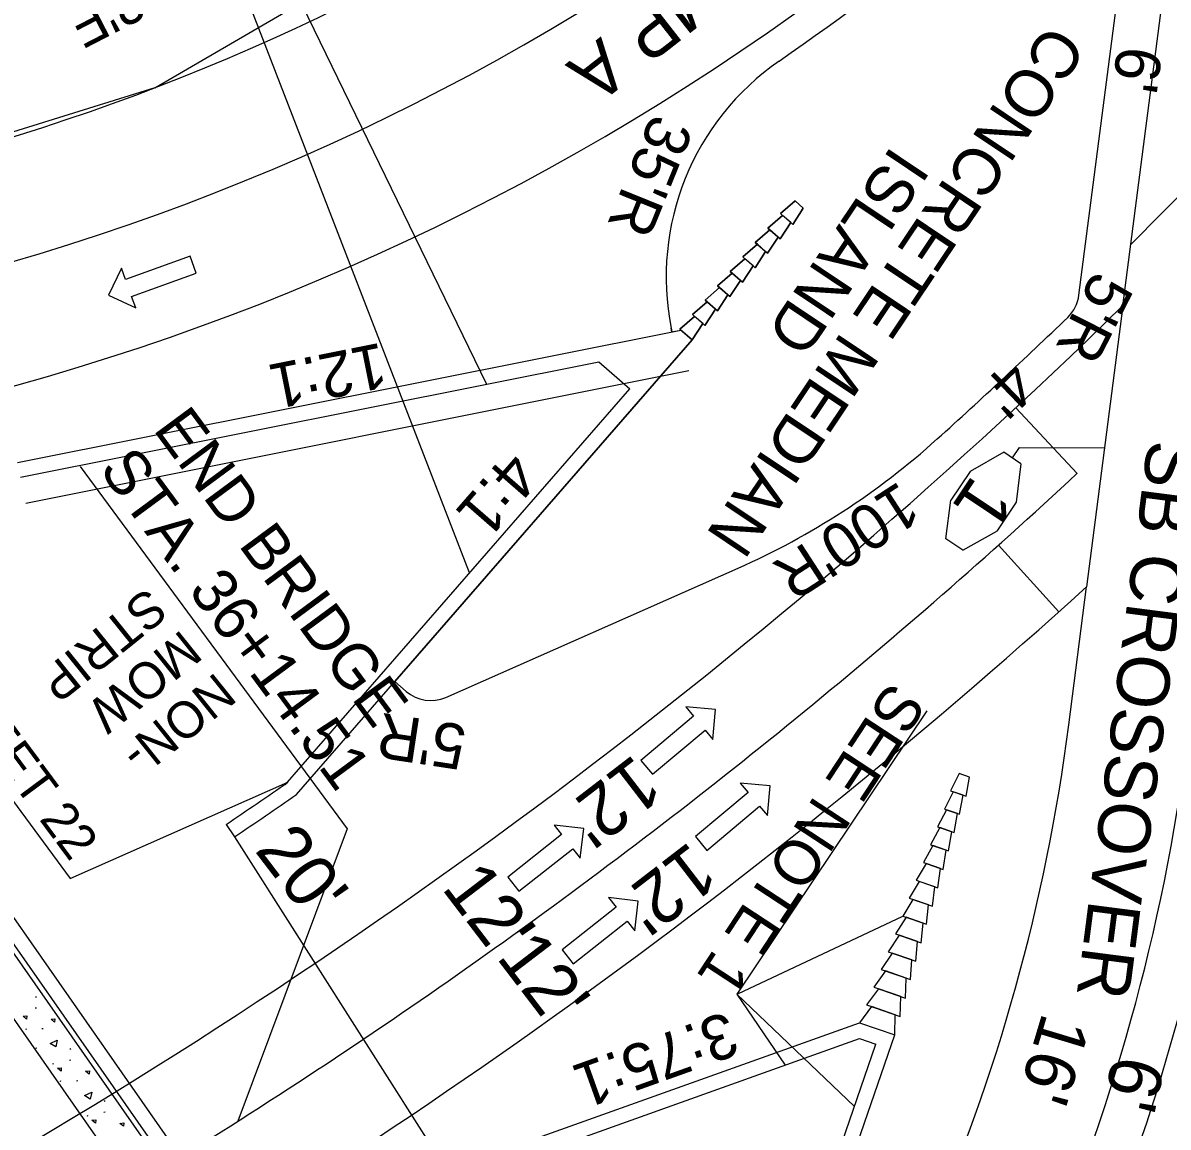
# Model space of a CAD drawing. Extents: x 1966090 to 1975830, y 788086 to 801233.
# Drawn here: x 1971441.1 to 1971594, y 796145.9 to 796293.3 of the extents above; entities that cross this region are included whole.
import ezdxf

# ---------------------------------------------------------------- set-up
doc = ezdxf.new("R2010")
doc.units = 0
for name, color, linetype in [('BR_PRESTRESSED BEAM', 7, 'Continuous'), ('BR_PROPOSED_DRAINAGE', 7, 'Continuous'), ('BR_PROPOSED_TRAVELWAY', 7, 'Continuous'), ('BR_REBAR', 7, 'Continuous'), ('BR_SITE LOCATION', 7, 'Continuous'), ('RD_EX_Driveway_txCode', 7, 'Continuous'), ('RD_EX_SU_Gas', 7, 'Continuous'), ('RD_EX_SU_SwpLmt', 7, 'Continuous'), ('RD_EX_TX_BldgApp_ELEV', 7, 'Continuous'), ('RD_EX_TX_Dam_ELEV', 7, 'Continuous'), ('RD_HY_XS_Slope', 7, 'Continuous'), ('RD_PD_RW_TX', 7, 'Continuous'), ('RD_Sketch6', 7, 'Continuous'), ('RD_Sketch8', 7, 'Continuous')]:
    doc.layers.add(name, color=color, linetype=linetype)

msp = doc.modelspace()

# ---------------------------------------------------------------- linework, layer by layer
at = {"layer": 'BR_PRESTRESSED BEAM'}
for q in [(1971520.97, 796320.88), (1971423.44, 796273.61)]:
    msp.add_line((1971458.75, 796284.65), q, dxfattribs=at)
at = {"layer": 'BR_PROPOSED_DRAINAGE'}
msp.add_lwpolyline([(1971355.49, 796296.53), (1971379.93, 796260.39), (1971397.2, 796235.33), (1971416.64, 796207.13), (1971494.67, 796095.38), (1971512.27, 796070.43)], dxfattribs=at)
at = {"layer": 'BR_PROPOSED_TRAVELWAY'}
for p, q in [((1971582.1, 796256.96), (1971587.53, 796299.08)), ((1971582.1, 796256.96), (1971587.53, 796299.08)), ((1971542.26, 796267.85), (1971544.21, 796269.54)), ((1971545.31, 796268.58), (1971543.91, 796266.41)), ((1971544.21, 796269.54), (1971545.31, 796268.58)), ((1971540.58, 796265.92), (1971542.53, 796267.61)), ((1971542.53, 796267.61), (1971542.26, 796267.85)), ((1971538.9, 796264), (1971540.86, 796265.68)), ((1971540.86, 796265.68), (1971540.58, 796265.92)), ((1971543.64, 796266.65), (1971542.23, 796264.48)), ((1971543.91, 796266.41), (1971543.64, 796266.65)), ((1971539.18, 796263.76), (1971538.9, 796264)), ((1971541.96, 796264.72), (1971540.55, 796262.56)), ((1971542.23, 796264.48), (1971541.96, 796264.72)), ((1971537.22, 796262.07), (1971539.18, 796263.76)), ((1971540.28, 796262.8), (1971538.88, 796260.63)), ((1971540.55, 796262.56), (1971540.28, 796262.8)), ((1971535.55, 796260.14), (1971537.5, 796261.83)), ((1971538.6, 796260.87), (1971537.2, 796258.7)), ((1971537.5, 796261.83), (1971537.22, 796262.07)), ((1971538.88, 796260.63), (1971538.6, 796260.87)), ((1971533.87, 796258.21), (1971535.82, 796259.9)), ((1971535.82, 796259.9), (1971535.55, 796260.14)), ((1971532.19, 796256.29), (1971534.14, 796257.97)), ((1971534.14, 796257.97), (1971533.87, 796258.21)), ((1971536.92, 796258.94), (1971535.52, 796256.78)), ((1971537.2, 796258.7), (1971536.92, 796258.94)), ((1971532.47, 796256.05), (1971532.19, 796256.29)), ((1971535.24, 796257.01), (1971533.84, 796254.85)), ((1971535.52, 796256.78), (1971535.24, 796257.01)), ((1971530.51, 796254.36), (1971532.47, 796256.05)), ((1971533.57, 796255.09), (1971532.16, 796252.92)), ((1971533.84, 796254.85), (1971533.57, 796255.09)), ((1971528.83, 796252.43), (1971530.79, 796254.12)), ((1971531.89, 796253.16), (1971530.49, 796250.99)), ((1971530.79, 796254.12), (1971530.51, 796254.36)), ((1971532.16, 796252.92), (1971531.89, 796253.16)), ((1971527.78, 796252.07), (1971527.68, 796252.57)), ((1971527.68, 796252.57), (1971527.78, 796252.07)), ((1971527.78, 796252.07), (1971528.98, 796252.31)), ((1971528.98, 796252.31), (1971528.83, 796252.43)), ((1971530.49, 796250.99), (1971490.78, 796205.39)), ((1971497.59, 796203.27), (1971536.62, 796220.53)), ((1971497.59, 796203.27), (1971536.62, 796220.53)), ((1971490.78, 796205.39), (1971492.29, 796204.08)), ((1971490.78, 796205.39), (1971492.29, 796204.08))]:
    msp.add_line(p, q, dxfattribs=at)
for points in [[(1971538.6, 796260.87), (1971538.6, 796260.87)], [(1971536.92, 796258.94), (1971536.92, 796258.94)], [(1971535.24, 796257.01), (1971535.24, 796257.01)], [(1971530.79, 796254.12), (1971530.79, 796254.12)], [(1971531.89, 796253.16), (1971531.89, 796253.16)]]:
    msp.add_lwpolyline(points, dxfattribs=at)
for centre, radius, start, end in [((1971352.19, 796562.97), 334, 304.6524, 315.4027), ((1971352.19, 796562.97), 334, 304.6524, 315.4027), ((1971562, 796259.42), 35, 124.6524, 191.2971), ((1971562, 796259.42), 35, 124.6524, 191.2971), ((1971577.14, 796257.6), 5, 313.8618, 352.6496), ((1971577.14, 796257.6), 5, 313.8618, 352.6496), ((1971051.22, 796804.85), 764, 312.07619, 313.8618), ((1971051.22, 796804.85), 764, 312.07619, 313.8618), ((1971496.17, 796311.99), 100, 293.8568, 312.0762), ((1971496.17, 796311.99), 100, 293.8568, 312.0762), ((1971495.57, 796207.85), 5, 228.9555, 293.8568), ((1971495.57, 796207.85), 5, 228.9555, 293.8568)]:
    msp.add_arc(centre, radius, start, end, dxfattribs=at)
at = {"layer": 'BR_REBAR'}
for p, q in [((1971440.43, 796234.62), (1971528.98, 796252.31)), ((1971530.49, 796250.99), (1971528.98, 796252.31)), ((1971477.65, 796190.31), (1971530.49, 796250.99)), ((1971440.82, 796232.66), (1971518, 796248.07)), ((1971518, 796248.07), (1971522.15, 796244.46)), ((1971476.14, 796191.62), (1971522.15, 796244.46)), ((1971468.28, 796186.32), (1971469.39, 796184.66)), ((1971502.52, 796141.9), (1971552.8, 796159.85)), ((1971552.8, 796159.85), (1971557.52, 796158.22)), ((1971503.19, 796140.02), (1971552.81, 796157.73)), ((1971536.89, 796104.51), (1971554.98, 796156.98)), ((1971538.78, 796103.86), (1971557.52, 796158.22)), ((1971552.81, 796157.73), (1971554.98, 796156.98))]:
    msp.add_line(p, q, dxfattribs=at)
for points in [[(1971358.49, 796293.18), (1971359.61, 796291.14), (1971363.68, 796284.48), (1971364.94, 796282.55), (1971379.93, 796260.39), (1971397.2, 796235.33), (1971416.64, 796207.13), (1971494.67, 796095.38), (1971512.27, 796070.43)], [(1971356.73, 796292.22), (1971357.88, 796290.13), (1971361.99, 796283.41), (1971363.28, 796281.44), (1971378.28, 796259.26), (1971395.55, 796234.19), (1971414.99, 796205.99), (1971493.03, 796094.24), (1971510.62, 796069.31)]]:
    msp.add_lwpolyline(points, dxfattribs=at)
for centre, radius, start, end in [((1971051.22, 796804.85), 746, 303.99104, 304.75703), ((1971051.22, 796804.85), 748, 303.99104, 304.75703), ((1971332.81, 796231.61), 272, 336.2104, 348.0583)]:
    msp.add_arc(centre, radius, start, end, dxfattribs=at)
at = {"layer": 'BR_SITE LOCATION'}
for p, q in [((1971442.94, 796163.32), (1971442.81, 796163.22)), ((1971442.76, 796161.82), (1971442.94, 796161.85)), ((1971441.57, 796159.02), (1971441.51, 796158.89)), ((1971443.68, 796159.06), (1971443.86, 796159.09)), ((1971442.82, 796156.47), (1971443, 796156.5)), ((1971447.54, 796156.38), (1971447.41, 796156.27)), ((1971445.18, 796154.4), (1971445.13, 796154.28)), ((1971447.36, 796154.87), (1971447.54, 796154.9)), ((1971446.17, 796152.07), (1971446.12, 796151.94)), ((1971448.28, 796152.11), (1971448.46, 796152.14)), ((1971447.46, 796149.53), (1971447.6, 796149.55)), ((1971452.14, 796149.43), (1971452.01, 796149.32)), ((1971451.96, 796147.92), (1971452.14, 796147.95)), ((1971449.78, 796147.46), (1971449.73, 796147.33))]:
    msp.add_line(p, q, dxfattribs=at)
for points in [[(1971356.11, 796291.89), (1971357.26, 796289.78), (1971361.39, 796283.03), (1971362.69, 796281.05), (1971377.69, 796258.87), (1971394.97, 796233.79), (1971414.41, 796205.59), (1971492.45, 796093.83), (1971517.1, 796058.89)], [(1971351.73, 796289.49), (1971352.93, 796287.27), (1971357.17, 796280.35), (1971358.53, 796278.28), (1971373.56, 796256.05), (1971390.85, 796230.96), (1971410.3, 796202.74), (1971488.36, 796090.96), (1971513.02, 796056.01)], [(1971441.16, 796160.72), (1971441.67, 796160.79), (1971441.64, 796160.33), (1971441.16, 796160.72)], [(1971444.9, 796160.31), (1971445.41, 796160.38), (1971445.38, 796159.92), (1971444.9, 796160.31)], [(1971444.76, 796157.07), (1971445.72, 796157.54), (1971445.52, 796156.61), (1971444.78, 796157.06)], [(1971445.76, 796153.77), (1971446.27, 796153.84), (1971446.24, 796153.38), (1971445.76, 796153.77)], [(1971449.5, 796153.36), (1971450.01, 796153.43), (1971449.98, 796152.97), (1971449.5, 796153.36)], [(1971449.36, 796150.13), (1971450.32, 796150.59), (1971450.12, 796149.66), (1971449.38, 796150.12)], [(1971450.36, 796146.82), (1971450.87, 796146.89), (1971450.84, 796146.43), (1971450.36, 796146.82)], [(1971454.1, 796146.41), (1971454.61, 796146.48), (1971454.59, 796146.02), (1971454.1, 796146.41)]]:
    msp.add_lwpolyline(points, dxfattribs=at)
at = {"layer": 'RD_EX_Driveway_txCode'}
for points in [[(1971464.28, 796259.91), (1971463.46, 796262.17), (1971454.84, 796259.04), (1971454.28, 796260.58), (1971452.58, 796256.95), (1971456.21, 796255.26), (1971455.65, 796256.79)], [(1971523.63, 796194.87), (1971525.18, 796193.03), (1971532.21, 796198.91), (1971533.25, 796197.66), (1971533.61, 796201.65), (1971529.62, 796202), (1971530.67, 796200.75)], [(1971530.91, 796184.69), (1971532.45, 796182.85), (1971539.48, 796188.74), (1971540.53, 796187.49), (1971540.88, 796191.47), (1971536.9, 796191.82), (1971537.94, 796190.58)], [(1971505.85, 796179.28), (1971507.33, 796177.4), (1971514.54, 796183.08), (1971515.54, 796181.8), (1971516.01, 796185.77), (1971512.04, 796186.24), (1971513.05, 796184.96)], [(1971513.11, 796169.59), (1971514.6, 796167.71), (1971521.8, 796173.39), (1971522.81, 796172.11), (1971523.28, 796176.08), (1971519.31, 796176.55), (1971520.32, 796175.27)]]:
    msp.add_lwpolyline(points, close=True, dxfattribs=at)
at = {"layer": 'RD_EX_SU_Gas'}
for p, q in [((1971607.58, 796282.5), (1971589.03, 796263.74)), ((1971587.97, 796255.56), (1971583.13, 796218.05)), ((1971573.66, 796241.91), (1971581.87, 796233.18)), ((1971571.36, 796223.6), (1971579.43, 796214.69))]:
    msp.add_line(p, q, dxfattribs=at)
for start, end in [(305.76044, 312.8692), (298.92325, 306.04973)]:
    msp.add_arc((1971051.22, 796804.85), 780, start, end, dxfattribs=at)
at = {"layer": 'RD_EX_TX_BldgApp_ELEV'}
for p, q in [((1971544.21, 796269.54), (1971542.26, 796267.85)), ((1971543.91, 796266.41), (1971545.31, 796268.58)), ((1971545.31, 796268.58), (1971544.21, 796269.54)), ((1971542.53, 796267.61), (1971540.58, 796265.92)), ((1971542.26, 796267.85), (1971543.91, 796266.41)), ((1971543.64, 796266.65), (1971542.53, 796267.61)), ((1971540.86, 796265.68), (1971538.9, 796264)), ((1971540.58, 796265.92), (1971542.23, 796264.48)), ((1971541.96, 796264.72), (1971540.86, 796265.68)), ((1971542.23, 796264.48), (1971543.64, 796266.65)), ((1971538.9, 796264), (1971540.55, 796262.56)), ((1971540.55, 796262.56), (1971541.96, 796264.72)), ((1971539.18, 796263.76), (1971537.22, 796262.07)), ((1971538.88, 796260.63), (1971540.28, 796262.8)), ((1971540.28, 796262.8), (1971539.18, 796263.76)), ((1971537.5, 796261.83), (1971535.55, 796260.14)), ((1971537.2, 796258.7), (1971538.6, 796260.87)), ((1971537.22, 796262.07), (1971538.88, 796260.63)), ((1971538.6, 796260.87), (1971537.5, 796261.83)), ((1971535.82, 796259.9), (1971533.87, 796258.21)), ((1971535.55, 796260.14), (1971537.2, 796258.7)), ((1971536.92, 796258.94), (1971535.82, 796259.9)), ((1971536.37, 796259.42), (1971536.37, 796259.42)), ((1971534.14, 796257.97), (1971532.19, 796256.29)), ((1971533.87, 796258.21), (1971535.52, 796256.78)), ((1971535.24, 796257.01), (1971534.14, 796257.97)), ((1971535.52, 796256.78), (1971536.92, 796258.94)), ((1971532.19, 796256.29), (1971533.84, 796254.85)), ((1971533.84, 796254.85), (1971535.24, 796257.01)), ((1971532.47, 796256.05), (1971530.51, 796254.36)), ((1971532.16, 796252.92), (1971533.57, 796255.09)), ((1971533.57, 796255.09), (1971532.47, 796256.05)), ((1971530.79, 796254.12), (1971528.83, 796252.43)), ((1971530.49, 796250.99), (1971531.89, 796253.16)), ((1971530.51, 796254.36), (1971532.16, 796252.92)), ((1971531.89, 796253.16), (1971530.79, 796254.12)), ((1971528.83, 796252.43), (1971530.49, 796250.99)), ((1971566.13, 796193.1), (1971564.95, 796190.8)), ((1971567.51, 796192.62), (1971566.13, 796193.1)), ((1971567.03, 796190.09), (1971567.51, 796192.62)), ((1971565.33, 796190.67), (1971564.17, 796188.37)), ((1971564.95, 796190.8), (1971567.03, 796190.09)), ((1971566.65, 796190.22), (1971565.33, 796190.67)), ((1971566.14, 796187.69), (1971566.65, 796190.22)), ((1971564.42, 796188.28), (1971563.22, 796185.99)), ((1971564.17, 796188.37), (1971566.14, 796187.69)), ((1971565.89, 796187.77), (1971564.42, 796188.28)), ((1971565.43, 796185.23), (1971565.89, 796187.77)), ((1971563.22, 796185.99), (1971565.43, 796185.23)), ((1971563.51, 796185.89), (1971562.27, 796183.61)), ((1971565.14, 796185.33), (1971563.51, 796185.89)), ((1971564.71, 796182.78), (1971565.14, 796185.33)), ((1971562.6, 796183.5), (1971561.33, 796181.24)), ((1971562.27, 796183.61), (1971564.71, 796182.78)), ((1971564.38, 796182.89), (1971562.6, 796183.5)), ((1971563.99, 796180.32), (1971564.38, 796182.89)), ((1971561.69, 796181.11), (1971560.38, 796178.86)), ((1971561.33, 796181.24), (1971563.99, 796180.32)), ((1971563.62, 796180.45), (1971561.69, 796181.11)), ((1971563.27, 796177.86), (1971563.62, 796180.45)), ((1971560.78, 796178.72), (1971559.43, 796176.49)), ((1971560.38, 796178.86), (1971563.27, 796177.86)), ((1971562.87, 796178), (1971560.78, 796178.72)), ((1971562.55, 796175.41), (1971562.87, 796178)), ((1971559.94, 796176.31), (1971558.58, 796174.08)), ((1971559.43, 796176.49), (1971562.55, 796175.41)), ((1971562.04, 796175.58), (1971559.94, 796176.31)), ((1971561.74, 796172.99), (1971562.04, 796175.58)), ((1971559.02, 796173.92), (1971557.61, 796171.71)), ((1971558.58, 796174.08), (1971561.74, 796172.99)), ((1971561.3, 796173.14), (1971559.02, 796173.92)), ((1971561.04, 796170.53), (1971561.3, 796173.14)), ((1971558.1, 796171.54), (1971556.65, 796169.33)), ((1971557.61, 796171.71), (1971561.04, 796170.53)), ((1971560.55, 796170.69), (1971558.1, 796171.54)), ((1971560.33, 796168.06), (1971560.55, 796170.69)), ((1971557.18, 796169.15), (1971555.69, 796166.96)), ((1971556.65, 796169.33), (1971560.33, 796168.06)), ((1971559.81, 796168.25), (1971557.18, 796169.15)), ((1971558.49, 796168.7), (1971558.49, 796168.7)), ((1971559.63, 796165.6), (1971559.81, 796168.25)), ((1971556.26, 796166.77), (1971554.72, 796164.59)), ((1971555.69, 796166.96), (1971559.63, 796165.6)), ((1971559.06, 796165.8), (1971556.26, 796166.77)), ((1971554.72, 796164.59), (1971558.93, 796163.14)), ((1971558.93, 796163.14), (1971559.06, 796165.8)), ((1971555.34, 796164.38), (1971553.76, 796162.22)), ((1971558.31, 796163.35), (1971555.34, 796164.38)), ((1971558.23, 796160.68), (1971558.31, 796163.35)), ((1971554.42, 796162), (1971552.8, 796159.85)), ((1971553.76, 796162.22), (1971558.23, 796160.68)), ((1971557.57, 796160.91), (1971554.42, 796162)), ((1971557.52, 796158.22), (1971557.57, 796160.91)), ((1971552.8, 796159.85), (1971557.52, 796158.22))]:
    msp.add_line(p, q, dxfattribs=at)
at = {"layer": 'RD_EX_TX_Dam_ELEV'}
msp.add_line((1971469.39, 796184.66), (1971498.39, 796139.08), dxfattribs=at)
at = {"layer": 'RD_HY_XS_Slope'}
for p, q in [((1971572.08, 796235.99), (1971567.58, 796233.43)), ((1971574.35, 796234.47), (1971572.08, 796235.99)), ((1971567.58, 796233.43), (1971565, 796229.58)), ((1971574.35, 796234.47), (1971573.7, 796229.33)), ((1971564.35, 796224.44), (1971565, 796229.58)), ((1971573.7, 796229.33), (1971571.12, 796225.48)), ((1971566.62, 796222.92), (1971564.35, 796224.44)), ((1971566.62, 796222.92), (1971571.12, 796225.48))]:
    msp.add_line(p, q, dxfattribs=at)
msp.add_lwpolyline([(1971573.22, 796235.23), (1971574.16, 796236.63), (1971585.52, 796236.59)], dxfattribs=at)
at = {"layer": 'RD_PD_RW_TX'}
msp.add_arc((1971352.19, 796562.97), 298, 221.212, 301.3407, dxfattribs=at)
at = {"layer": 'RD_Sketch6'}
for p, q in [((1971500.77, 796219.91), (1971444.18, 796366.06)), ((1971441.51, 796229.22), (1971530.05, 796246.91)), ((1971448.78, 796234.11), (1971484.44, 796185.74)), ((1971561.79, 796201.49), (1971536.45, 796163.65)), ((1971484.44, 796185.74), (1971469.84, 796146.7)), ((1971536.56, 796163.7), (1971558.58, 796174.08)), ((1971536.45, 796163.65), (1971552.12, 796148.68)), ((1971536.45, 796163.65), (1971542.9, 796154.19))]:
    msp.add_line(p, q, dxfattribs=at)
for points in [[(1971471.47, 796406.81), (1971444.18, 796366.06), (1971503.03, 796245.08)], [(1971419.46, 796217.05), (1971447.43, 796179.11), (1971476.51, 796191.95)]]:
    msp.add_lwpolyline(points, dxfattribs=at)
at = {"layer": 'RD_Sketch8'}
for p, q in [((1971587.97, 796255.56), (1971593.49, 796298.31)), ((1971580.76, 796199.63), (1971583.13, 796218.05))]:
    msp.add_line(p, q, dxfattribs=at)
for centre, radius, start, end in [((1971352.19, 796562.97), 314, 221.212, 318.863), ((1971352.19, 796562.97), 330, 221.212, 316.8104), ((1971051.22, 796804.85), 768, 298.92325, 314.33883), ((1971051.22, 796804.85), 792, 298.92325, 312.19164), ((1971332.81, 796231.61), 250, 336.2104, 352.6496), ((1971332.81, 796231.61), 266, 336.2104, 352.6496)]:
    msp.add_arc(centre, radius, start, end, dxfattribs=at)

# ---------------------------------------------------------------- texts
at = {"layer": 'RD_EX_Driveway_txCode'}
for s, height, rotation, p in [('RAMP A', 7, 218.0606, (1971541.66, 796309.8)), ('CONCRETE MEDIAN', 6.3, 236.1913, (1971578.04, 796293.45)), ("6'", 6, 262.6496, (1971587.28, 796290.37)), ("35'R", 6, 247.9747, (1971525.17, 796281.41)), ('ISLAND', 6.3, 236.1913, (1971557.15, 796277.09)), ("5'R", 6, 243.2557, (1971584.18, 796260.45)), ('12:1', 6, 191.2971, (1971488.97, 796250.65)), ("4'", 6, 223.8618, (1971572.83, 796248.62)), ('SB CROSSOVER', 7, 262.651, (1971591.36, 796237.79)), ('4:1', 6, 228.9555, (1971506, 796236.45)), ("100'R", 6, 212.9665, (1971558.18, 796232.24)), ("5'R", 6, 171.4061, (1971500.58, 796199.48)), ("12'", 7, 217.566, (1971522.78, 796195.83)), ("20'", 7, 307.3614, (1971471.97, 796182.86)), ("12'", 7, 217.566, (1971530.21, 796184.19)), ("12'", 7, 307.3614, (1971496.92, 796177.82)), ("12'", 7, 307.3614, (1971504.23, 796168.57)), ('3:75:1', 6, 199.6476, (1971535.16, 796161.46)), ("16'", 6.667, 253.2712, (1971577.28, 796161.38)), ("6'", 7, 257.9132, (1971586.75, 796155.76))]:
    msp.add_text(s, height=height, rotation=rotation, dxfattribs=at).set_placement(p)
at = {"layer": 'RD_EX_SU_SwpLmt'}
msp.add_text("133'F", height=5.4, rotation=207.2915, dxfattribs=at).set_placement((1971462.66, 796302.79))
at = {"layer": 'RD_HY_XS_Slope'}
msp.add_text('1', height=7, rotation=236.2115, dxfattribs=at).set_placement((1971567.96, 796233.15))
at = {"layer": 'RD_Sketch6'}
for s, height, rotation, p in [('END BRIDGE', 6, 306.4243, (1971458.43, 796239.05)), ('STA. 36+14.51', 5.9996, 306.4243, (1971451.19, 796233.7)), ('SEE SHEET 22', 4.8596, 306.5574, (1971420.43, 796217.77)), ('STRIP', 4.86, 218.7979, (1971457.8, 796218.11)), ('MOW', 4.86, 218.7979, (1971462.37, 796212.43)), ('NON-', 4.86, 218.7979, (1971466.93, 796206.75)), ('SEE NOTE 1', 6, 236.7151, (1971556.91, 796205.63))]:
    msp.add_text(s, height=height, rotation=rotation, dxfattribs=at).set_placement(p)

doc.saveas('drawing.dxf')
